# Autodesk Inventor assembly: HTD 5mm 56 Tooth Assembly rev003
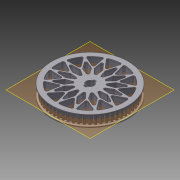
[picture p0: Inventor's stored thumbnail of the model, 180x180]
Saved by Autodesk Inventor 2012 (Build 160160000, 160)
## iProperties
Created: 2012-01
Part Number: HTD 5mm 56 Tooth Assembly rev003
Document SubType Name: Assembly
Designer: Alex
Author: Alex
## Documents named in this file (3)
- C:\Users\Owner\Documents\Robotics\Mechanical Design\Parts\pulley\HTD\56\HTD 5mm 56 Tooth Assembly rev003.iam
- C:\Users\Owner\Documents\Robotics\Mechanical Design\Parts\pulley\HTD\56\HTD 5mm 56 Tooth Flange_rev001.ipt
- C:\Users\Owner\Documents\Robotics\Mechanical Design\Parts\pulley\HTD\56\HTD 5mm 56 Tooth rev001 step 3.ipt
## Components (3 placed, 2 different names)
1. HTD 5mm 56 Tooth Flange_rev001:1 — Mate:1, Mate:2, Flush:2, Flush:3
2. HTD 5mm 56 Tooth rev001 step 3:1 — Mate:1, Mate:2, Flush:1, Insert:1
3. HTD 5mm 56 Tooth Flange_rev001:2 — Insert:1
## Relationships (6: Flush 3, Mate 2, Insert 1)
- Mate:1: HTD 5mm 56 Tooth Flange_rev001:1 ↔ HTD 5mm 56 Tooth rev001 step 3:1
- Mate:2: HTD 5mm 56 Tooth Flange_rev001:1 ↔ HTD 5mm 56 Tooth rev001 step 3:1
- Flush:1: HTD 5mm 56 Tooth rev001 step 3:1
- Flush:2: HTD 5mm 56 Tooth Flange_rev001:1
- Flush:3: HTD 5mm 56 Tooth Flange_rev001:1
- Insert:1: HTD 5mm 56 Tooth rev001 step 3:1 ↔ HTD 5mm 56 Tooth Flange_rev001:2
